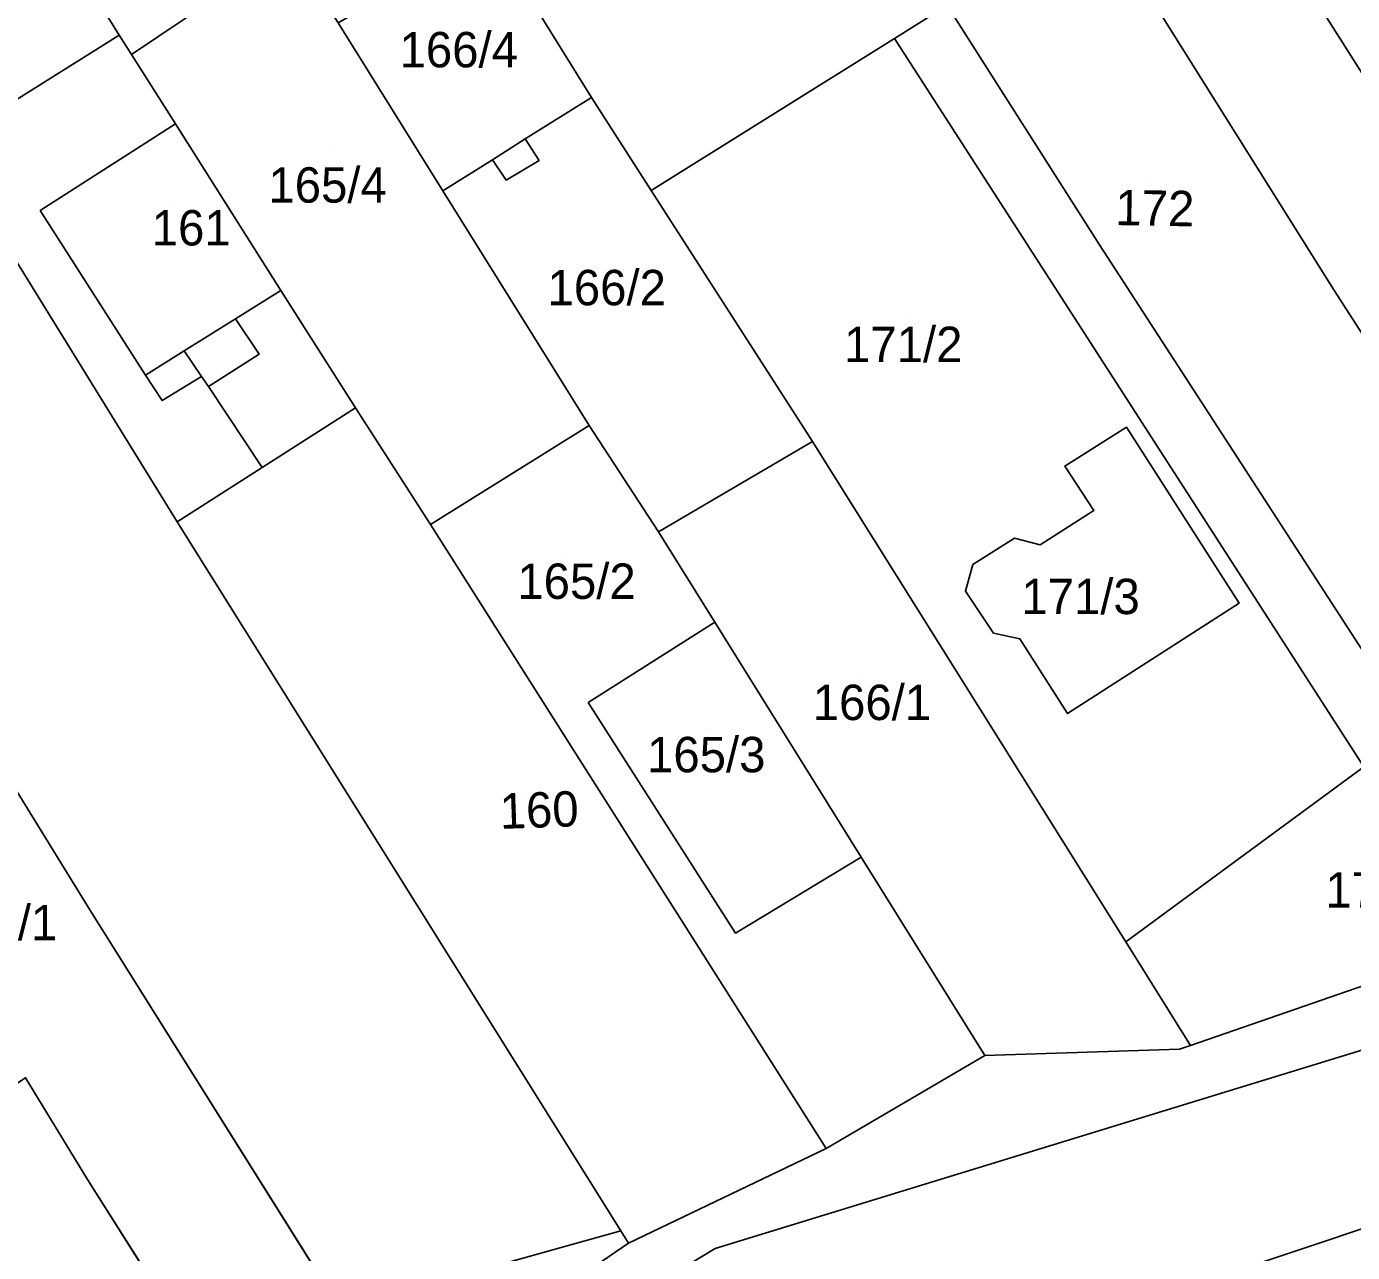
# Model space of a CAD drawing. Extents: x -263943 to -261149, y -1236934 to -1230686.
# Drawn here: x -262471.2 to -262396.2, y -1235851.1 to -1235781.8 of the extents above; entities that cross this region are included whole.
import ezdxf

# ---------------------------------------------------------------- set-up
doc = ezdxf.new("R2010")
doc.units = 0
for name, color, linetype in [('body_kn', 7, 'Continuous'), ('kladpar_druhypozemkov', 7, 'Continuous'), ('kladpar_hranice', 7, 'Continuous'), ('kladpar_parcelnecisla', 7, 'Continuous'), ('kladpar_plochy', 7, 'Continuous'), ('zappar_hrandruhpozemk', 7, 'Continuous')]:
    doc.layers.add(name, color=color, linetype=linetype)

msp = doc.modelspace()

# ---------------------------------------------------------------- linework, layer by layer
at = {"layer": 'body_kn'}
for p, q in [((-262465.95, -1235782.28), (-262465.95, -1235782.28)), ((-262422.11, -1235782.46), (-262422.11, -1235782.46)), ((-262422.11, -1235782.46), (-262422.11, -1235782.46)), ((-262465.26, -1235783.37), (-262465.26, -1235783.37)), ((-262439.25, -1235785.8), (-262439.25, -1235785.8)), ((-262462.77, -1235787.3), (-262462.77, -1235787.3)), ((-262462.77, -1235787.3), (-262462.77, -1235787.3)), ((-262442.99, -1235788.15), (-262442.99, -1235788.15)), ((-262442.99, -1235788.15), (-262442.99, -1235788.15)), ((-262444.84, -1235789.32), (-262444.84, -1235789.32)), ((-262442.21, -1235789.36), (-262442.21, -1235789.36)), ((-262444.07, -1235790.47), (-262444.07, -1235790.47)), ((-262447.65, -1235791.09), (-262447.65, -1235791.09)), ((-262447.65, -1235791.09), (-262447.65, -1235791.09)), ((-262435.87, -1235791.07), (-262435.87, -1235791.07)), ((-262435.87, -1235791.07), (-262435.87, -1235791.07)), ((-262470.41, -1235792.2), (-262470.41, -1235792.2)), ((-262410.52, -1235794.14), (-262410.52, -1235794.14)), ((-262456.81, -1235796.71), (-262456.81, -1235796.71)), ((-262397.29, -1235796.67), (-262397.29, -1235796.67)), ((-262459.37, -1235798.31), (-262459.37, -1235798.31)), ((-262462.27, -1235800.13), (-262462.27, -1235800.13)), ((-262462.27, -1235800.13), (-262462.27, -1235800.13)), ((-262458.03, -1235800.31), (-262458.03, -1235800.31)), ((-262464.46, -1235801.5), (-262464.46, -1235801.5)), ((-262464.46, -1235801.5), (-262464.46, -1235801.5)), ((-262461.29, -1235801.58), (-262461.29, -1235801.58)), ((-262460.91, -1235802.15), (-262460.91, -1235802.15)), ((-262460.91, -1235802.15), (-262460.91, -1235802.15)), ((-262463.53, -1235802.94), (-262463.53, -1235802.94)), ((-262452.6, -1235803.35), (-262452.6, -1235803.35)), ((-262439.38, -1235804.35), (-262439.38, -1235804.35)), ((-262409.01, -1235804.45), (-262409.01, -1235804.45)), ((-262426.76, -1235805.26), (-262426.76, -1235805.26)), ((-262426.76, -1235805.26), (-262426.76, -1235805.26)), ((-262457.86, -1235806.72), (-262457.86, -1235806.72)), ((-262412.49, -1235806.64), (-262412.49, -1235806.64)), ((-262410.85, -1235809.16), (-262410.85, -1235809.16)), ((-262462.67, -1235809.8), (-262462.67, -1235809.8)), ((-262462.67, -1235809.8), (-262462.67, -1235809.8)), ((-262448.35, -1235809.95), (-262448.35, -1235809.95)), ((-262435.47, -1235810.35), (-262435.47, -1235810.35)), ((-262415.33, -1235810.72), (-262415.33, -1235810.72)), ((-262413.89, -1235811.09), (-262413.89, -1235811.09)), ((-262417.69, -1235812.21), (-262417.69, -1235812.21)), ((-262418.11, -1235813.71), (-262418.11, -1235813.71)), ((-262402.63, -1235814.39), (-262402.63, -1235814.39)), ((-262432.28, -1235815.47), (-262432.28, -1235815.47)), ((-262416.52, -1235816.09), (-262416.52, -1235816.09)), ((-262415.03, -1235816.4), (-262415.03, -1235816.4)), ((-262439.43, -1235820.01), (-262439.43, -1235820.01)), ((-262439.43, -1235820.01), (-262439.43, -1235820.01)), ((-262412.33, -1235820.63), (-262412.33, -1235820.63)), ((-262412.33, -1235820.63), (-262412.33, -1235820.63)), ((-262424, -1235828.76), (-262424, -1235828.76)), ((-262467.61, -1235831.73), (-262467.61, -1235831.73)), ((-262467.61, -1235831.73), (-262467.61, -1235831.73)), ((-262431.1, -1235833.04), (-262431.1, -1235833.04)), ((-262409.05, -1235833.54), (-262409.05, -1235833.54)), ((-262417.02, -1235839.96), (-262417.02, -1235839.96)), ((-262406.01, -1235839.61), (-262406.01, -1235839.61)), ((-262405.39, -1235839.39), (-262405.39, -1235839.39)), ((-262405.39, -1235839.39), (-262405.39, -1235839.39)), ((-262425.99, -1235845.22), (-262425.99, -1235845.22)), ((-262467.75, -1235846.97), (-262467.75, -1235846.97)), ((-262437.59, -1235849.88), (-262437.59, -1235849.88)), ((-262437.16, -1235850.57), (-262437.16, -1235850.57)), ((-262432.26, -1235850.87), (-262432.26, -1235850.87))]:
    msp.add_line(p, q, dxfattribs=at)
at = {"layer": 'kladpar_druhypozemkov'}
for p, q in [((-262453.83, -1235788.51), (-262453.83, -1235788.51)), ((-262407.67, -1235790.65), (-262407.67, -1235790.65)), ((-262463.08, -1235791.91), (-262463.08, -1235791.91)), ((-262438.97, -1235795.4), (-262438.97, -1235795.4)), ((-262421.51, -1235798.27), (-262421.51, -1235798.27)), ((-262440.62, -1235811.85), (-262440.62, -1235811.85)), ((-262411.51, -1235813.14), (-262411.51, -1235813.14)), ((-262424.27, -1235818.6), (-262424.27, -1235818.6)), ((-262432.77, -1235821.45), (-262432.77, -1235821.45)), ((-262442.86, -1235825.29), (-262442.86, -1235825.29))]:
    msp.add_line(p, q, dxfattribs=at)
at = {"layer": 'kladpar_hranice'}
msp.add_line((-262426.76, -1235805.26), (-262435.87, -1235791.07), dxfattribs=at)
for points in [[(-262379.1, -1235824.92), (-262397.29, -1235796.67), (-262418.29, -1235763.17), (-262430.23, -1235743.91), (-262431.98, -1235741.09), (-262442.29, -1235724.3), (-262438.67, -1235722.03), (-262438.04, -1235723.06), (-262436.85, -1235722.38), (-262437.54, -1235721.32), (-262436.26, -1235720.52), (-262438.35, -1235717.28), (-262437.77, -1235716.92), (-262415.1, -1235753.76), (-262391.97, -1235790.31), (-262374.2, -1235817.63), (-262379.1, -1235824.92)], [(-262221.35, -1235736.53), (-262215.31, -1235734.05), (-262214.73, -1235729.67), (-262212.23, -1235727.82), (-262196.44, -1235752.3), (-262205.08, -1235765.59), (-262287.96, -1235783.1), (-262324.59, -1235788.02), (-262348.24, -1235806.76), (-262382.26, -1235845.27), (-262431.3, -1235861.65), (-262462.1, -1235880.68), (-262481.52, -1235902.92), (-262487.28, -1235895.25), (-262479.81, -1235885.76), (-262471.14, -1235874.39), (-262432.26, -1235850.87), (-262383.35, -1235835.88), (-262353.66, -1235792.2), (-262322.94, -1235774.62), (-262282.99, -1235772.47), (-262248.29, -1235747.7), (-262221.35, -1235736.53)], [(-262422.11, -1235782.46), (-262435.87, -1235791.07), (-262439.25, -1235785.8), (-262444.99, -1235776.53), (-262448.94, -1235770.15), (-262455.49, -1235760), (-262457.88, -1235756.09), (-262440.95, -1235745.76), (-262438.78, -1235749.25), (-262426.84, -1235768.51), (-262419.14, -1235780.6), (-262422.11, -1235782.46)], [(-262374.2, -1235817.63), (-262391.97, -1235790.31), (-262415.1, -1235753.76), (-262404.61, -1235746.98), (-262394.66, -1235762.54), (-262381.57, -1235782.84), (-262367.03, -1235805.18)], [(-262470.83, -1235754.18), (-262463.76, -1235765.42), (-262456.27, -1235777.32), (-262465.26, -1235783.37), (-262465.95, -1235782.28), (-262480.48, -1235758.85), (-262471.52, -1235753.08), (-262470.83, -1235754.18)], [(-262493.36, -1235760.39), (-262483.46, -1235754.11), (-262480.48, -1235758.85), (-262465.95, -1235782.28), (-262475.84, -1235788.48), (-262490.4, -1235765.13), (-262493.36, -1235760.39)], [(-262379.1, -1235824.92), (-262385.61, -1235832.55), (-262410.52, -1235794.14), (-262419.14, -1235780.6), (-262426.84, -1235768.51), (-262418.29, -1235763.17), (-262397.29, -1235796.67), (-262379.1, -1235824.92)], [(-262467.61, -1235831.73), (-262477.05, -1235816.42), (-262492.69, -1235791.8), (-262504.11, -1235773.23), (-262490.4, -1235765.13), (-262475.84, -1235788.48), (-262462.67, -1235809.8), (-262437.59, -1235849.88), (-262453.44, -1235854.31), (-262467.61, -1235831.73)], [(-262442.99, -1235788.15), (-262442.21, -1235789.36), (-262444.07, -1235790.47), (-262444.84, -1235789.32), (-262447.65, -1235791.09), (-262453.58, -1235781.59), (-262450.92, -1235780.03), (-262451.55, -1235779.05), (-262448.42, -1235777.18), (-262447.78, -1235778.17), (-262444.99, -1235776.53), (-262439.25, -1235785.8), (-262442.99, -1235788.15)], [(-262447.65, -1235791.09), (-262439.38, -1235804.35), (-262448.35, -1235809.95), (-262452.6, -1235803.35), (-262456.81, -1235796.71), (-262462.77, -1235787.3), (-262465.26, -1235783.37), (-262456.27, -1235777.32), (-262453.58, -1235781.59), (-262447.65, -1235791.09)], [(-262395.59, -1235823.64), (-262422.11, -1235782.46), (-262419.14, -1235780.6), (-262410.52, -1235794.14), (-262385.61, -1235832.55), (-262405.39, -1235839.39), (-262409.05, -1235833.54), (-262395.59, -1235823.64)], [(-262462.67, -1235809.8), (-262475.84, -1235788.48), (-262465.95, -1235782.28), (-262465.26, -1235783.37), (-262462.77, -1235787.3), (-262456.81, -1235796.71), (-262452.6, -1235803.35), (-262457.86, -1235806.72), (-262462.67, -1235809.8)], [(-262435.87, -1235791.07), (-262422.11, -1235782.46), (-262395.59, -1235823.64), (-262409.05, -1235833.54), (-262426.76, -1235805.26)], [(-262426.76, -1235805.26), (-262435.47, -1235810.35), (-262439.38, -1235804.35), (-262447.65, -1235791.09), (-262444.84, -1235789.32), (-262444.07, -1235790.47), (-262442.21, -1235789.36), (-262442.99, -1235788.15), (-262439.25, -1235785.8), (-262435.87, -1235791.07), (-262426.76, -1235805.26)], [(-262458.14, -1235862.12), (-262467.75, -1235846.97), (-262471.24, -1235841.22), (-262475.72, -1235844.19), (-262500.01, -1235805.37), (-262504, -1235799), (-262492.69, -1235791.8), (-262477.05, -1235816.42), (-262467.61, -1235831.73), (-262453.44, -1235854.31), (-262450.19, -1235859.48)], [(-262462.67, -1235809.8), (-262457.86, -1235806.72), (-262452.6, -1235803.35), (-262448.35, -1235809.95), (-262425.99, -1235845.22), (-262437.16, -1235850.57), (-262437.59, -1235849.88), (-262462.67, -1235809.8)], [(-262439.43, -1235820.01), (-262431.1, -1235833.04), (-262424, -1235828.76), (-262417.02, -1235839.96), (-262425.99, -1235845.22), (-262448.35, -1235809.95), (-262439.38, -1235804.35), (-262435.47, -1235810.35), (-262432.28, -1235815.47), (-262439.43, -1235820.01)], [(-262409.01, -1235804.45), (-262412.49, -1235806.64), (-262410.85, -1235809.16), (-262413.89, -1235811.09), (-262415.33, -1235810.72), (-262417.69, -1235812.21), (-262418.11, -1235813.71), (-262416.52, -1235816.09), (-262415.03, -1235816.4), (-262412.33, -1235820.63), (-262402.63, -1235814.39), (-262409.01, -1235804.45)], [(-262412.33, -1235820.63), (-262415.03, -1235816.4), (-262416.52, -1235816.09), (-262418.11, -1235813.71), (-262417.69, -1235812.21), (-262415.33, -1235810.72), (-262413.89, -1235811.09), (-262410.85, -1235809.16), (-262412.49, -1235806.64), (-262409.01, -1235804.45), (-262402.63, -1235814.39), (-262412.33, -1235820.63)], [(-262405.39, -1235839.39), (-262406.01, -1235839.61), (-262417.02, -1235839.96), (-262424, -1235828.76), (-262432.28, -1235815.47), (-262435.47, -1235810.35), (-262426.76, -1235805.26), (-262409.05, -1235833.54), (-262405.39, -1235839.39)], [(-262439.43, -1235820.01), (-262432.28, -1235815.47), (-262424, -1235828.76), (-262431.1, -1235833.04), (-262439.43, -1235820.01)], [(-262481.15, -1235879.42), (-262471.34, -1235872.3), (-262464.32, -1235867.21), (-262458.14, -1235862.12), (-262450.19, -1235859.48), (-262437.16, -1235850.57), (-262425.99, -1235845.22), (-262417.02, -1235839.96), (-262406.01, -1235839.61), (-262405.39, -1235839.39), (-262385.61, -1235832.55)], [(-262383.35, -1235835.88), (-262432.26, -1235850.87), (-262471.14, -1235874.39), (-262479.81, -1235885.76), (-262487.28, -1235895.25), (-262488.64, -1235893.44), (-262490.28, -1235894.59), (-262497.06, -1235905.43), (-262532.6, -1235941.48), (-262554.01, -1235954.13), (-262556.15, -1235951.34), (-262521.02, -1235914.55), (-262499.91, -1235892.57), (-262496.55, -1235888.16), (-262489.14, -1235866.73), (-262481.15, -1235879.42)], [(-262476.98, -1235848.77), (-262478.26, -1235846.57), (-262475.72, -1235844.19), (-262471.24, -1235841.22), (-262467.75, -1235846.97), (-262458.14, -1235862.12), (-262464.32, -1235867.21), (-262476.98, -1235848.77)], [(-262431.3, -1235861.65), (-262382.26, -1235845.27)], [(-262453.44, -1235854.31), (-262437.59, -1235849.88), (-262437.16, -1235850.57), (-262450.19, -1235859.48), (-262453.44, -1235854.31)]]:
    msp.add_lwpolyline(points, dxfattribs=at)
at = {"layer": 'kladpar_plochy'}
for p, q in [((-262391.97, -1235790.31), (-262415.1, -1235753.76)), ((-262435.87, -1235791.07), (-262422.11, -1235782.46)), ((-262422.11, -1235782.46), (-262395.59, -1235823.64)), ((-262426.76, -1235805.26), (-262435.87, -1235791.07)), ((-262409.01, -1235804.45), (-262412.49, -1235806.64)), ((-262402.63, -1235814.39), (-262409.01, -1235804.45)), ((-262409.05, -1235833.54), (-262426.76, -1235805.26)), ((-262412.49, -1235806.64), (-262410.85, -1235809.16)), ((-262410.85, -1235809.16), (-262413.89, -1235811.09)), ((-262415.33, -1235810.72), (-262417.69, -1235812.21)), ((-262413.89, -1235811.09), (-262415.33, -1235810.72)), ((-262417.69, -1235812.21), (-262418.11, -1235813.71)), ((-262418.11, -1235813.71), (-262416.52, -1235816.09)), ((-262412.33, -1235820.63), (-262402.63, -1235814.39)), ((-262477.05, -1235816.42), (-262467.61, -1235831.73)), ((-262416.52, -1235816.09), (-262415.03, -1235816.4)), ((-262415.03, -1235816.4), (-262412.33, -1235820.63)), ((-262395.59, -1235823.64), (-262409.05, -1235833.54)), ((-262467.61, -1235831.73), (-262453.44, -1235854.31)), ((-262467.75, -1235846.97), (-262471.24, -1235841.22)), ((-262458.14, -1235862.12), (-262467.75, -1235846.97))]:
    msp.add_line(p, q, dxfattribs=at)
for points in [[(-262379.1, -1235824.92), (-262397.29, -1235796.67), (-262418.29, -1235763.17), (-262430.23, -1235743.91), (-262431.98, -1235741.09), (-262442.29, -1235724.3), (-262438.67, -1235722.03), (-262438.04, -1235723.06), (-262436.85, -1235722.38), (-262437.54, -1235721.32), (-262436.26, -1235720.52), (-262438.35, -1235717.28), (-262437.77, -1235716.92), (-262415.1, -1235753.76), (-262391.97, -1235790.31), (-262374.2, -1235817.63)], [(-262221.35, -1235736.53), (-262215.31, -1235734.05), (-262214.73, -1235729.67), (-262212.23, -1235727.82), (-262196.44, -1235752.3), (-262205.08, -1235765.59), (-262287.96, -1235783.1), (-262324.59, -1235788.02), (-262348.24, -1235806.76), (-262382.26, -1235845.27), (-262431.3, -1235861.65), (-262462.1, -1235880.68), (-262481.52, -1235902.92), (-262487.28, -1235895.25), (-262479.81, -1235885.76), (-262471.14, -1235874.39), (-262432.26, -1235850.87), (-262383.35, -1235835.88), (-262353.66, -1235792.2), (-262322.94, -1235774.62), (-262282.99, -1235772.47), (-262248.29, -1235747.7)], [(-262422.11, -1235782.46), (-262435.87, -1235791.07), (-262439.25, -1235785.8), (-262444.99, -1235776.53), (-262448.94, -1235770.15), (-262455.49, -1235760), (-262457.88, -1235756.09), (-262440.95, -1235745.76), (-262438.78, -1235749.25), (-262426.84, -1235768.51), (-262419.14, -1235780.6)], [(-262470.83, -1235754.18), (-262463.76, -1235765.42), (-262456.27, -1235777.32), (-262465.26, -1235783.37), (-262465.95, -1235782.28), (-262480.48, -1235758.85), (-262471.52, -1235753.08)], [(-262493.36, -1235760.39), (-262483.46, -1235754.11), (-262480.48, -1235758.85), (-262465.95, -1235782.28), (-262475.84, -1235788.48), (-262490.4, -1235765.13)], [(-262379.1, -1235824.92), (-262385.61, -1235832.55), (-262410.52, -1235794.14), (-262419.14, -1235780.6), (-262426.84, -1235768.51), (-262418.29, -1235763.17), (-262397.29, -1235796.67)], [(-262467.61, -1235831.73), (-262477.05, -1235816.42), (-262492.69, -1235791.8), (-262504.11, -1235773.23), (-262490.4, -1235765.13), (-262475.84, -1235788.48), (-262462.67, -1235809.8), (-262437.59, -1235849.88), (-262453.44, -1235854.31)], [(-262442.99, -1235788.15), (-262442.21, -1235789.36), (-262444.07, -1235790.47), (-262444.84, -1235789.32), (-262447.65, -1235791.09), (-262453.58, -1235781.59), (-262450.92, -1235780.03), (-262451.55, -1235779.05), (-262448.42, -1235777.18), (-262447.78, -1235778.17), (-262444.99, -1235776.53), (-262439.25, -1235785.8)], [(-262447.65, -1235791.09), (-262439.38, -1235804.35), (-262448.35, -1235809.95), (-262452.6, -1235803.35), (-262456.81, -1235796.71), (-262462.77, -1235787.3), (-262465.26, -1235783.37), (-262456.27, -1235777.32), (-262453.58, -1235781.59)], [(-262395.59, -1235823.64), (-262422.11, -1235782.46), (-262419.14, -1235780.6), (-262410.52, -1235794.14), (-262385.61, -1235832.55), (-262405.39, -1235839.39), (-262409.05, -1235833.54)], [(-262462.67, -1235809.8), (-262475.84, -1235788.48), (-262465.95, -1235782.28), (-262465.26, -1235783.37), (-262462.77, -1235787.3), (-262456.81, -1235796.71), (-262452.6, -1235803.35), (-262457.86, -1235806.72)], [(-262426.76, -1235805.26), (-262435.47, -1235810.35), (-262439.38, -1235804.35), (-262447.65, -1235791.09), (-262444.84, -1235789.32), (-262444.07, -1235790.47), (-262442.21, -1235789.36), (-262442.99, -1235788.15), (-262439.25, -1235785.8), (-262435.87, -1235791.07)], [(-262462.67, -1235809.8), (-262457.86, -1235806.72), (-262452.6, -1235803.35), (-262448.35, -1235809.95), (-262425.99, -1235845.22), (-262437.16, -1235850.57), (-262437.59, -1235849.88)], [(-262439.43, -1235820.01), (-262431.1, -1235833.04), (-262424, -1235828.76), (-262417.02, -1235839.96), (-262425.99, -1235845.22), (-262448.35, -1235809.95), (-262439.38, -1235804.35), (-262435.47, -1235810.35), (-262432.28, -1235815.47)], [(-262412.33, -1235820.63), (-262415.03, -1235816.4), (-262416.52, -1235816.09), (-262418.11, -1235813.71), (-262417.69, -1235812.21), (-262415.33, -1235810.72), (-262413.89, -1235811.09), (-262410.85, -1235809.16), (-262412.49, -1235806.64), (-262409.01, -1235804.45), (-262402.63, -1235814.39)], [(-262405.39, -1235839.39), (-262406.01, -1235839.61), (-262417.02, -1235839.96), (-262424, -1235828.76), (-262432.28, -1235815.47), (-262435.47, -1235810.35), (-262426.76, -1235805.26), (-262409.05, -1235833.54)], [(-262439.43, -1235820.01), (-262432.28, -1235815.47), (-262424, -1235828.76), (-262431.1, -1235833.04)], [(-262476.98, -1235848.77), (-262478.26, -1235846.57), (-262475.72, -1235844.19), (-262471.24, -1235841.22), (-262467.75, -1235846.97), (-262458.14, -1235862.12), (-262464.32, -1235867.21)], [(-262453.44, -1235854.31), (-262437.59, -1235849.88), (-262437.16, -1235850.57), (-262450.19, -1235859.48)]]:
    msp.add_lwpolyline(points, close=True, dxfattribs=at)
for points in [[(-262450.19, -1235859.48), (-262437.16, -1235850.57), (-262425.99, -1235845.22), (-262417.02, -1235839.96), (-262406.01, -1235839.61), (-262405.39, -1235839.39), (-262385.61, -1235832.55)], [(-262383.35, -1235835.88), (-262432.26, -1235850.87), (-262471.14, -1235874.39)], [(-262431.3, -1235861.65), (-262382.26, -1235845.27)]]:
    msp.add_lwpolyline(points, dxfattribs=at)
at = {"layer": 'zappar_hrandruhpozemk'}
for p, q in [((-262462.77, -1235787.3), (-262470.41, -1235792.2)), ((-262442.99, -1235788.15), (-262444.84, -1235789.32)), ((-262459.37, -1235798.31), (-262456.81, -1235796.71)), ((-262460.91, -1235802.15), (-262457.86, -1235806.72))]:
    msp.add_line(p, q, dxfattribs=at)
for points in [[(-262470.41, -1235792.2), (-262464.46, -1235801.5), (-262462.27, -1235800.13), (-262459.37, -1235798.31)], [(-262459.37, -1235798.31), (-262458.03, -1235800.31), (-262460.91, -1235802.15)], [(-262462.27, -1235800.13), (-262461.29, -1235801.58), (-262460.91, -1235802.15)], [(-262464.46, -1235801.5), (-262463.53, -1235802.94), (-262461.29, -1235801.58)]]:
    msp.add_lwpolyline(points, dxfattribs=at)

# ---------------------------------------------------------------- texts
at = {"layer": 'kladpar_parcelnecisla'}
for s, p in [('166/4', (-262450.1, -1235784.1)), ('165/4', (-262457.515, -1235791.75)), ('161', (-262464.11, -1235794.17)), ('166/2', (-262441.736, -1235797.55)), ('171/2', (-262424.97, -1235800.76)), ('165/2', (-262443.441, -1235814.15)), ('171/3', (-262414.945, -1235815.01)), ('166/1', (-262426.74, -1235821)), ('165/3', (-262436.107, -1235823.95)), ('171/1', (-262397.763, -1235831.6)), ('154/1', (-262476.145, -1235833.45))]:
    msp.add_text(s, height=2, dxfattribs=at).set_placement(p)
for s, rotation, p in [('172', 359, (-262409.646, -1235793.016)), ('160', 2, (-262444.405, -1235827.156))]:
    msp.add_text(s, height=2, rotation=rotation, dxfattribs=at).set_placement(p)

doc.saveas('drawing.dxf')
